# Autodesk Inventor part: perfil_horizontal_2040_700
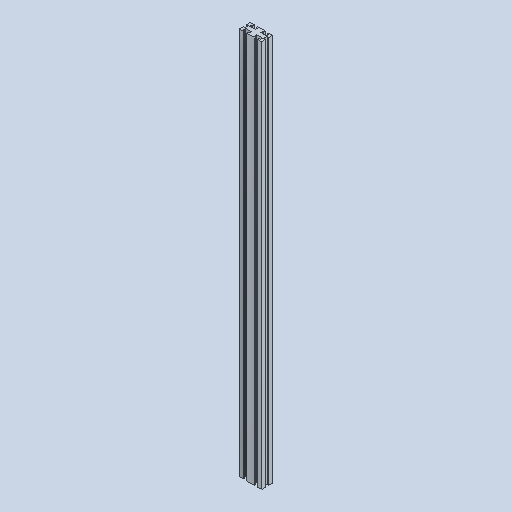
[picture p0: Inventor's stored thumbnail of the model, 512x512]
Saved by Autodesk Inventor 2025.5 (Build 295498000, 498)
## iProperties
Created: 2026-10
Part Number: perfil_horizontal_2040_700
Material: Genérico
Document SubType Name: Modeling
Designer: Luis M
Density: 1 g/cm^3
Appearance: Valor por defecto
Author: Luis M
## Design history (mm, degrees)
feature "Base1"
node "Sólido1"
